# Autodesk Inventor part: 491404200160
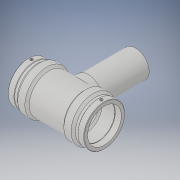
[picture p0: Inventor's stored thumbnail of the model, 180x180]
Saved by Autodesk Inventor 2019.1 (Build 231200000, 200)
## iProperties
Created: 2017-06
Part Number: 491404200160
Material: Generic
Description: PLASSON REDUCING TEE 200x160x200
Document SubType Name: Modeling
Designer: KIM
Mass: 5000.41 g
Surface Area: 5471.45 cm^2
Volume: 5000.41 cm^3
Density: 1 g/cm^3
Appearance: Default
Author: KIM
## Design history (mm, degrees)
derived "491404.ipt"
feature "Solid1::491404.ipt"
tag "TaggingFeature1"
body "Solid1"
other parameters: "d0" = 451, "d2" = 261, "d3" = 114, "d4" = 90.2, "d5" = 234.9, "d8" = 168 deg, "d10" = 45.6, "d11" = 15.2, "d13" = 451, "d14" = 17.6296, "d19" = 3.52592, "d20" = 168 deg, "d22" = 242.73, "d23" = 261, "d25" = 135 deg, "d26" = 315.7, "d29" = 125, "d30" = 15, "d31" = 180.4, "d34" = 5 deg, "d35" = 15, "d39" = 5 deg, "d41" = 4, "d42" = 14, "d43" = 0, "d45" = 4, "d46" = 6, "d47" = 0, "d51" = 0, "d52" = 128, "d54" = 0, "d55" = 234.9, "d56" = 261, "d57" = 157.85, "d58" = 135 deg, "d59" = 114, "d60" = 114, "d61" = 135 deg, "d72" = 205.205, "d73" = 102.6025, "d75" = 168, "d77" = 0, "d78" = 128, "d80" = 0, "d82" = 279.5, "d83" = 0, "d84" = 3, "d85" = 0, "d86" = 38, "d87" = 237.8754, "d88" = 15.2, "d89" = 3, "d90" = 0, "L_" = 451, "L_1" = 114, "D_" = 261, "A_" = 125, "d_2" = 12
